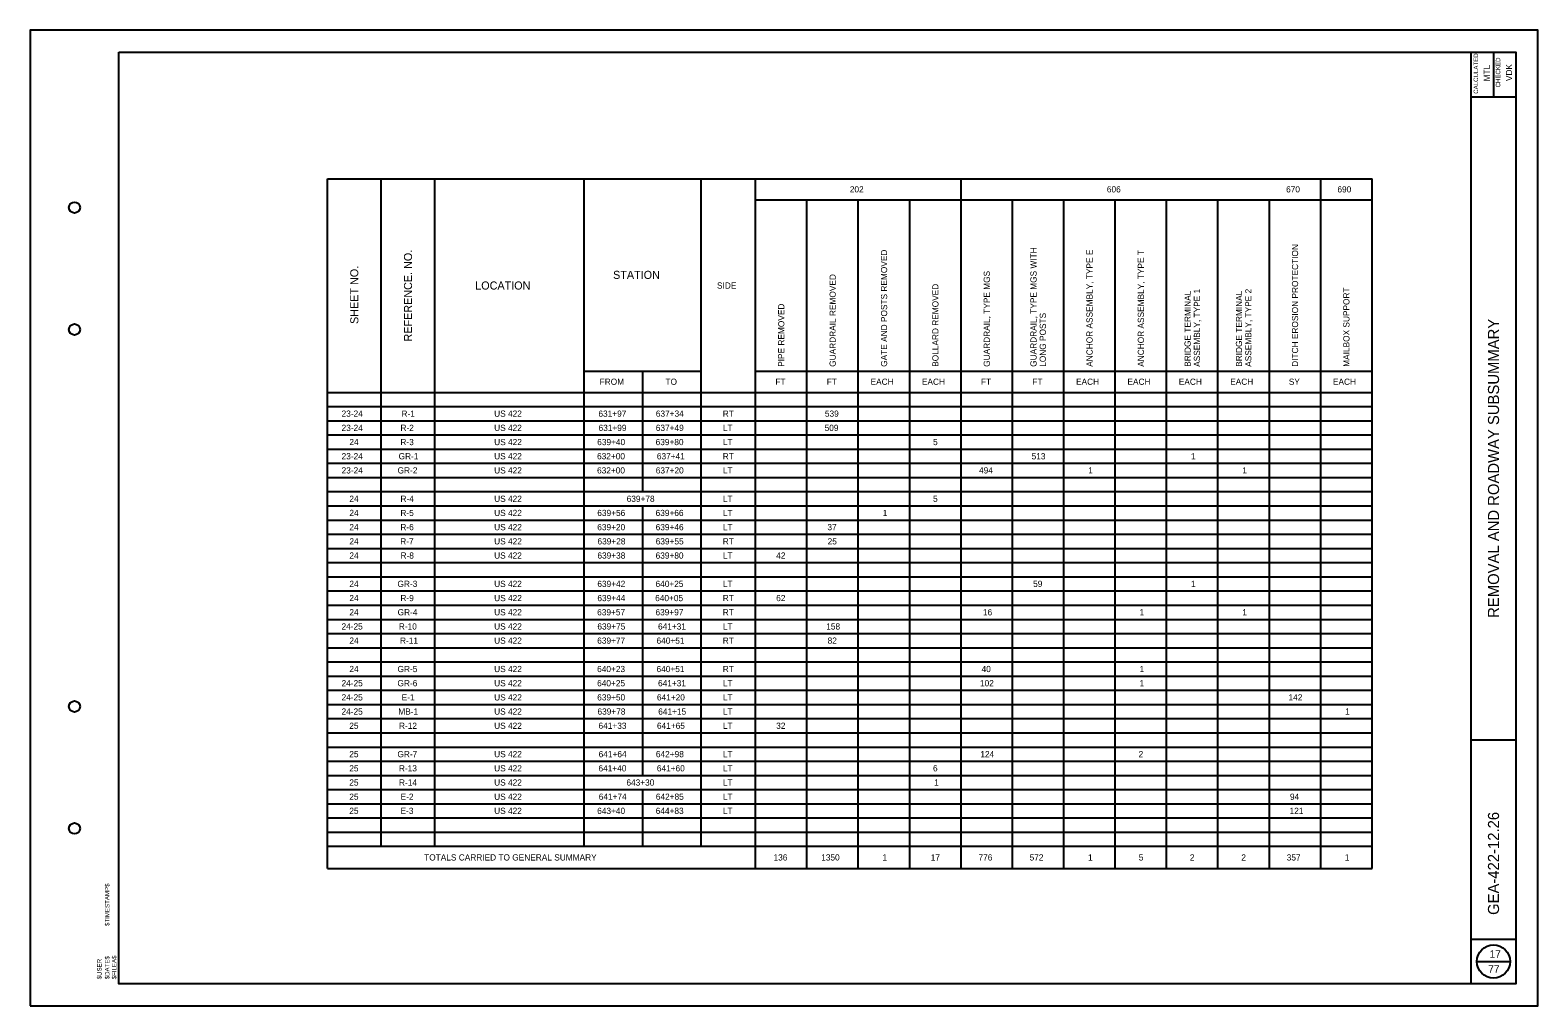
# Model space of a CAD drawing. Extents: x 0 to 34, y 0 to 22.
import ezdxf

# ---------------------------------------------------------------- set-up
doc = ezdxf.new("R2010")
doc.units = 0
for name, color, linetype in [('SH_Border', 7, 'Continuous'), ('SH_Cut_Line', 7, 'Continuous'), ('SH_Data', 7, 'Continuous'), ('SH_Text', 7, 'Continuous')]:
    doc.layers.add(name, color=color, linetype=linetype)

msp = doc.modelspace()

# ---------------------------------------------------------------- linework, layer by layer
at = {"layer": 'SH_Border'}
for p, q in [((32.5, 0.5), (32.5, 21.5)), ((33, 21.5), (33, 20.5)), ((32.5, 20.5), (33.5, 20.5)), ((32.5, 6), (33.5, 6)), ((32.5, 1.5), (33.5, 1.5))]:
    msp.add_line(p, q, dxfattribs=at)
msp.add_lwpolyline([(2, 21.5), (33.5, 21.5), (33.5, 0.5), (2, 0.5)], close=True, dxfattribs=at)
for centre in [(1, 18), (1, 15.25), (1, 6.75), (1, 4)]:
    msp.add_circle(centre, 0.125, dxfattribs=at)
at = {"layer": 'SH_Cut_Line'}
msp.add_lwpolyline([(0, 0), (34, 0), (34, 22), (0, 22)], close=True, dxfattribs=at)
at = {"layer": 'SH_Data'}
msp.add_line((32.625, 1), (33.375, 1), dxfattribs=at)
msp.add_circle((33, 1), 0.375, dxfattribs=at)
at = {"layer": 'SH_Text'}
for p, q in [((6.705, 18.651), (6.705, 18.651)), ((6.705, 18.651), (30.262, 18.651)), ((6.705, 3.097), (6.705, 18.651)), ((7.916, 3.597), (7.916, 18.651)), ((9.127, 3.597), (9.127, 18.651)), ((12.497, 3.597), (12.497, 18.651)), ((15.13, 3.597), (15.13, 18.651)), ((16.359, 3.097), (16.359, 18.651)), ((20.993, 3.097), (20.993, 18.651)), ((29.103, 3.097), (29.103, 18.651)), ((30.262, 3.097), (30.262, 18.651)), ((16.359, 18.171), (30.262, 18.171)), ((17.518, 3.097), (17.518, 18.171)), ((18.676, 3.097), (18.676, 18.171)), ((19.835, 3.097), (19.835, 18.171)), ((22.152, 3.097), (22.152, 18.171)), ((23.31, 3.097), (23.31, 18.171)), ((24.469, 3.097), (24.469, 18.171)), ((25.628, 3.097), (25.628, 18.171)), ((26.786, 3.097), (26.786, 18.171)), ((27.945, 3.097), (27.945, 18.171)), ((12.497, 14.313), (15.13, 14.313)), ((13.814, 11.594), (13.814, 14.313)), ((16.359, 14.313), (30.262, 14.313)), ((6.705, 13.833), (30.262, 13.833)), ((15.13, 13.833), (30.262, 13.833)), ((6.705, 13.513), (30.262, 13.513)), ((6.705, 13.193), (30.262, 13.193)), ((6.705, 12.873), (30.262, 12.873)), ((6.705, 12.553), (30.262, 12.553)), ((6.705, 12.233), (30.262, 12.233)), ((6.705, 11.914), (30.262, 11.914)), ((6.705, 11.594), (30.262, 11.594)), ((6.705, 11.274), (30.262, 11.274)), ((13.814, 5.196), (13.814, 11.274)), ((6.705, 10.954), (30.262, 10.954)), ((6.705, 10.634), (30.262, 10.634)), ((6.705, 10.314), (30.262, 10.314)), ((6.705, 9.994), (30.262, 9.994)), ((6.705, 9.674), (30.262, 9.674)), ((6.705, 9.355), (30.262, 9.355)), ((6.705, 9.035), (30.262, 9.035)), ((6.705, 8.715), (30.262, 8.715)), ((6.705, 8.395), (30.262, 8.395)), ((6.705, 8.075), (30.262, 8.075)), ((6.705, 7.755), (30.262, 7.755)), ((6.705, 7.435), (30.262, 7.435)), ((6.705, 7.116), (30.262, 7.116)), ((6.705, 6.796), (30.262, 6.796)), ((6.705, 6.476), (30.262, 6.476)), ((6.705, 6.156), (30.262, 6.156)), ((6.705, 5.836), (30.262, 5.836)), ((6.705, 5.516), (30.262, 5.516)), ((6.705, 5.196), (30.262, 5.196)), ((6.705, 4.876), (30.262, 4.876)), ((13.814, 3.597), (13.814, 4.876)), ((6.705, 4.557), (30.262, 4.557)), ((6.705, 4.237), (30.262, 4.237)), ((6.705, 3.917), (30.262, 3.917)), ((6.705, 3.597), (30.262, 3.597)), ((6.705, 3.097), (30.262, 3.097))]:
    msp.add_line(p, q, dxfattribs=at)

# ---------------------------------------------------------------- texts
at = {"layer": 'SH_Data'}
for s, height, rotation, p in [('CALCULATED', 0.1, 90, (32.652, 20.565)), ('MTL', 0.14, 90, (32.92, 20.844)), ('CHECKED', 0.1, 90, (33.152, 20.708)), ('VDK', 0.14, 90, (33.42, 20.851)), ('REMOVAL AND ROADWAY SUBSUMMARY', 0.25, 90, (33.125, 8.749)), (' GEA-422-12.26 ', 0.25, 90, (33.125, 1.957)), ('$TIMESTAMP$', 0.1, 89.9931, (1.788, 1.8)), ('$USER', 0.1, 89.9931, (1.611, 0.598)), ('$DATE$', 0.1, 89.9931, (1.788, 0.598)), ('$FILEA$', 0.1, 89.9931, (1.944, 0.598))]:
    msp.add_text(s, height=height, rotation=rotation, dxfattribs=at).set_placement(p)
for s, p in [('17', (32.914, 1.085)), ('77', (32.882, 0.745))]:
    msp.add_text(s, height=0.17, dxfattribs=at).set_placement(p)
at = {"layer": 'SH_Text'}
for s, height, p in [('202', 0.14, (18.484, 18.341)), ('606', 0.14, (24.281, 18.341)), ('670', 0.14, (28.323, 18.341)), ('690', 0.14, (29.48, 18.341)), ('LOCATION', 0.182, (10.037, 16.151)), ('STATION', 0.182, (13.146, 16.391)), ('SIDE', 0.14, (15.489, 16.172)), ('FROM', 0.14, (12.843, 14.003)), ('TO', 0.14, (14.327, 14.003)), ('FT', 0.14, (16.807, 14.003)), ('FT', 0.14, (17.965, 14.003)), ('EACH', 0.14, (18.952, 14.003)), ('EACH', 0.14, (20.11, 14.003)), ('FT', 0.14, (21.441, 14.003)), ('FT', 0.14, (22.599, 14.003)), ('EACH', 0.14, (23.586, 14.003)), ('EACH', 0.14, (24.745, 14.003)), ('EACH', 0.14, (25.903, 14.003)), ('EACH', 0.14, (27.062, 14.003)), ('SY', 0.14, (28.384, 14.003)), ('EACH', 0.14, (29.379, 14.003)), ('23-24', 0.14, (7.023, 13.283)), ('R-1', 0.14, (8.374, 13.283)), ('US 422', 0.14, (10.464, 13.283)), ('631+97', 0.14, (12.815, 13.283)), ('637+34', 0.14, (14.11, 13.283)), ('RT', 0.14, (15.619, 13.283)), ('539', 0.14, (17.922, 13.283)), ('23-24', 0.14, (7.023, 12.963)), ('R-2', 0.14, (8.351, 12.963)), ('US 422', 0.14, (10.464, 12.963)), ('631+99', 0.14, (12.818, 12.963)), ('637+49', 0.14, (14.109, 12.963)), ('LT', 0.14, (15.622, 12.963)), ('509', 0.14, (17.916, 12.963)), ('24', 0.14, (7.199, 12.643)), ('R-3', 0.14, (8.349, 12.643)), ('US 422', 0.14, (10.464, 12.643)), ('639+40', 0.14, (12.788, 12.643)), ('639+80', 0.14, (14.105, 12.643)), ('LT', 0.14, (15.622, 12.643)), ('5', 0.14, (20.361, 12.643)), ('23-24', 0.14, (7.023, 12.323)), ('GR-1', 0.14, (8.309, 12.323)), ('US 422', 0.14, (10.464, 12.323)), ('632+00', 0.14, (12.784, 12.323)), ('637+41', 0.14, (14.133, 12.323)), ('RT', 0.14, (15.619, 12.323)), ('513', 0.14, (22.584, 12.323)), ('1', 0.14, (26.178, 12.323)), ('23-24', 0.14, (7.023, 12.004)), ('GR-2', 0.14, (8.286, 12.004)), ('US 422', 0.14, (10.464, 12.004)), ('632+00', 0.14, (12.784, 12.004)), ('637+20', 0.14, (14.108, 12.004)), ('LT', 0.14, (15.622, 12.004)), ('494', 0.14, (21.398, 12.004)), ('1', 0.14, (23.861, 12.004)), ('1', 0.14, (27.336, 12.004)), ('24', 0.14, (7.199, 11.364)), ('R-4', 0.14, (8.351, 11.364)), ('US 422', 0.14, (10.464, 11.364)), ('639+78', 0.14, (13.452, 11.364)), ('LT', 0.14, (15.622, 11.364)), ('5', 0.14, (20.361, 11.364)), ('24', 0.14, (7.199, 11.044)), ('R-5', 0.14, (8.35, 11.044)), ('US 422', 0.14, (10.464, 11.044)), ('639+56', 0.14, (12.79, 11.044)), ('639+66', 0.14, (14.105, 11.044)), ('LT', 0.14, (15.622, 11.044)), ('1', 0.14, (19.226, 11.044)), ('24', 0.14, (7.199, 10.724)), ('24', 0.14, (7.199, 10.404)), ('R-7', 0.14, (8.346, 10.404)), ('R-6', 0.14, (8.349, 10.724)), ('US 422', 0.14, (10.464, 10.724)), ('US 422', 0.14, (10.464, 10.404)), ('639+20', 0.14, (12.789, 10.724)), ('639+28', 0.14, (12.794, 10.404)), ('639+46', 0.14, (14.106, 10.724)), ('639+55', 0.14, (14.107, 10.404)), ('RT', 0.14, (15.619, 10.404)), ('LT', 0.14, (15.622, 10.724)), ('37', 0.14, (17.979, 10.724)), ('25', 0.14, (17.984, 10.404)), ('24', 0.14, (7.199, 10.084)), ('R-8', 0.14, (8.352, 10.084)), ('US 422', 0.14, (10.464, 10.084)), ('639+38', 0.14, (12.792, 10.084)), ('639+80', 0.14, (14.105, 10.084)), ('LT', 0.14, (15.622, 10.084)), ('42', 0.14, (16.825, 10.084)), ('24', 0.14, (7.199, 9.445)), ('GR-3', 0.14, (8.284, 9.445)), ('US 422', 0.14, (10.464, 9.445)), ('639+42', 0.14, (12.791, 9.445)), ('640+25', 0.14, (14.103, 9.445)), ('LT', 0.14, (15.622, 9.445)), ('59', 0.14, (22.618, 9.445)), ('1', 0.14, (26.178, 9.445)), ('24', 0.14, (7.199, 9.125)), ('R-9', 0.14, (8.35, 9.125)), ('US 422', 0.14, (10.464, 9.125)), ('639+44', 0.14, (12.791, 9.125)), ('640+05', 0.14, (14.095, 9.125)), ('RT', 0.14, (15.619, 9.125)), ('62', 0.14, (16.824, 9.125)), ('24', 0.14, (7.199, 8.805)), ('GR-4', 0.14, (8.287, 8.805)), ('US 422', 0.14, (10.464, 8.805)), ('639+57', 0.14, (12.787, 8.805)), ('639+97', 0.14, (14.102, 8.805)), ('RT', 0.14, (15.619, 8.805)), ('16', 0.14, (21.486, 8.805)), ('1', 0.14, (25.019, 8.805)), ('1', 0.14, (27.336, 8.805)), ('24-25', 0.14, (7.022, 8.485)), ('R-10', 0.14, (8.314, 8.485)), ('US 422', 0.14, (10.464, 8.485)), ('639+75', 0.14, (12.791, 8.485)), ('641+31', 0.14, (14.159, 8.485)), ('LT', 0.14, (15.622, 8.485)), ('158', 0.14, (17.953, 8.485)), ('24', 0.14, (7.199, 8.165)), ('R-11', 0.14, (8.341, 8.165)), ('US 422', 0.14, (10.464, 8.165)), ('639+77', 0.14, (12.788, 8.165)), ('640+51', 0.14, (14.126, 8.165)), ('RT', 0.14, (15.619, 8.165)), ('82', 0.14, (17.984, 8.165)), ('24', 0.14, (7.199, 7.525)), ('GR-5', 0.14, (8.285, 7.525)), ('US 422', 0.14, (10.464, 7.525)), ('640+23', 0.14, (12.786, 7.525)), ('640+51', 0.14, (14.126, 7.525)), ('RT', 0.14, (15.619, 7.525)), ('40', 0.14, (21.456, 7.525)), ('1', 0.14, (25.019, 7.525)), ('24-25', 0.14, (7.022, 7.205)), ('GR-6', 0.14, (8.284, 7.205)), ('US 422', 0.14, (10.464, 7.205)), ('640+25', 0.14, (12.786, 7.205)), ('641+31', 0.14, (14.159, 7.205)), ('LT', 0.14, (15.622, 7.205)), ('102', 0.14, (21.42, 7.205)), ('1', 0.14, (25.019, 7.205)), ('24-25', 0.14, (7.022, 6.886)), ('E-1', 0.14, (8.378, 6.886)), ('US 422', 0.14, (10.464, 6.886)), ('639+50', 0.14, (12.788, 6.886)), ('641+20', 0.14, (14.135, 6.886)), ('LT', 0.14, (15.622, 6.886)), ('142', 0.14, (28.377, 6.886)), ('24-25', 0.14, (7.022, 6.566)), ('MB-1', 0.14, (8.302, 6.566)), ('US 422', 0.14, (10.464, 6.566)), ('639+78', 0.14, (12.794, 6.566)), ('641+15', 0.14, (14.164, 6.566)), ('LT', 0.14, (15.622, 6.566)), ('1', 0.14, (29.653, 6.566)), ('25', 0.14, (7.197, 6.246)), ('R-12', 0.14, (8.318, 6.246)), ('US 422', 0.14, (10.464, 6.246)), ('641+33', 0.14, (12.818, 6.246)), ('641+65', 0.14, (14.135, 6.246)), ('LT', 0.14, (15.622, 6.246)), ('32', 0.14, (16.824, 6.246)), ('25', 0.14, (7.197, 5.606)), ('GR-7', 0.14, (8.282, 5.606)), ('US 422', 0.14, (10.464, 5.606)), ('641+64', 0.14, (12.82, 5.606)), ('642+98', 0.14, (14.111, 5.606)), ('LT', 0.14, (15.622, 5.606)), ('124', 0.14, (21.428, 5.606)), ('2', 0.14, (24.996, 5.606)), ('25', 0.14, (7.197, 5.286)), ('25', 0.14, (7.197, 4.966)), ('R-13', 0.14, (8.316, 5.286)), ('R-14', 0.14, (8.318, 4.966)), ('US 422', 0.14, (10.464, 5.286)), ('US 422', 0.14, (10.464, 4.966)), ('641+40', 0.14, (12.817, 5.286)), ('643+30', 0.14, (13.446, 4.966)), ('641+60', 0.14, (14.133, 5.286)), ('LT', 0.14, (15.622, 5.286)), ('LT', 0.14, (15.622, 4.966)), ('6', 0.14, (20.36, 5.286)), ('1', 0.14, (20.385, 4.966)), ('25', 0.14, (7.197, 4.646)), ('E-2', 0.14, (8.354, 4.646)), ('US 422', 0.14, (10.464, 4.646)), ('641+74', 0.14, (12.822, 4.646)), ('642+85', 0.14, (14.11, 4.646)), ('LT', 0.14, (15.622, 4.646)), ('94', 0.14, (28.41, 4.646)), ('25', 0.14, (7.197, 4.327)), ('E-3', 0.14, (8.353, 4.327)), ('US 422', 0.14, (10.464, 4.327)), ('643+40', 0.14, (12.788, 4.327)), ('644+83', 0.14, (14.107, 4.327)), ('LT', 0.14, (15.622, 4.327)), ('121', 0.14, (28.402, 4.327)), ('TOTALS CARRIED TO GENERAL SUMMARY', 0.14, (8.885, 3.277)), ('136', 0.14, (16.764, 3.277)), ('1350', 0.14, (17.839, 3.277)), ('1', 0.14, (19.221, 3.277)), ('17', 0.14, (20.309, 3.277)), ('776', 0.14, (21.386, 3.277)), ('572', 0.14, (22.539, 3.277)), ('1', 0.14, (23.856, 3.277)), ('5', 0.14, (25.001, 3.277)), ('2', 0.14, (26.154, 3.277)), ('2', 0.14, (27.313, 3.277)), ('357', 0.14, (28.337, 3.277)), ('1', 0.14, (29.648, 3.277))]:
    msp.add_text(s, height=height, dxfattribs=at).set_placement(p)
for s, height, p in [('REFERENCE. NO.', 0.182, (8.612, 14.98)), ('GATE AND POSTS REMOVED', 0.14, (19.326, 14.409)), ('GUARDRAIL, TYPE MGS WITH', 0.14, (22.696, 14.409)), ('ANCHOR ASSEMBLY, TYPE E', 0.14, (23.96, 14.409)), ('ANCHOR ASSEMBLY, TYPE T', 0.14, (25.118, 14.409)), ('DITCH EROSION PROTECTION', 0.14, (28.594, 14.409)), ('SHEET NO.', 0.182, (7.401, 15.375)), ('GUARDRAIL REMOVED', 0.14, (18.167, 14.409)), ('GUARDRAIL, TYPE MGS', 0.14, (21.643, 14.409)), ('BOLLARD REMOVED', 0.14, (20.484, 14.409)), ('BRIDGE TERMINAL', 0.14, (26.172, 14.409)), ('ASSEMBLY, TYPE 1 ', 0.14, (26.382, 14.409)), ('BRIDGE TERMINAL', 0.14, (27.33, 14.409)), ('ASSEMBLY, TYPE 2', 0.14, (27.54, 14.409)), ('MAILBOX SUPPORT', 0.14, (29.752, 14.409)), ('PIPE REMOVED', 0.14, (17.008, 14.409)), ('LONG POSTS', 0.14, (22.906, 14.409))]:
    msp.add_text(s, height=height, rotation=90, dxfattribs=at).set_placement(p)

doc.saveas('drawing.dxf')
